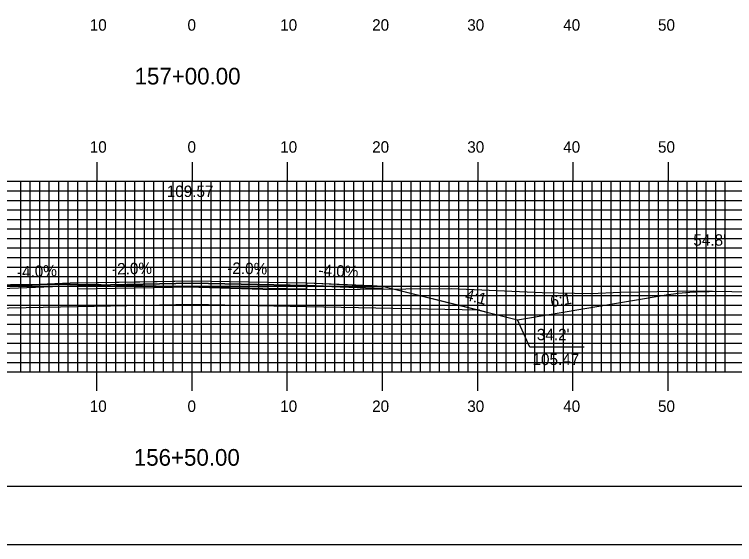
# Model space of a CAD drawing. Extents: x 1779499 to 1779842, y 442591 to 442811.
# Drawn here: x 1779646.2 to 1779721.8, y 442590.5 to 442646.2 of the extents above; entities that cross this region are included whole.
import ezdxf

# ---------------------------------------------------------------- set-up
doc = ezdxf.new("R2010")
doc.units = 0
for name, color, linetype in [('ANNOTATION', 7, 'Continuous'), ('BORDER', 7, 'Continuous'), ('D_Roadway_Centerline', 7, 'Continuous'), ('D_Roadway_Centerline_Text', 7, 'Continuous'), ('D_Roadway_Edge_Shoulder', 7, 'Continuous'), ('D_Roadway_Edge_TW', 7, 'Continuous'), ('D_Roadway_Pavement', 7, 'Continuous'), ('D_Roadway_SlopeLines', 7, 'Continuous'), ('D_Roadway_SubGrade', 7, 'Continuous'), ('D_Text_Standard', 7, 'Continuous'), ('H_V ANNOTATION', 7, 'Continuous'), ('MAJOR', 7, 'Continuous'), ('MINOR', 7, 'Continuous'), ('PLOT BOUNDARY', 7, 'Continuous'), ('S_Roadway_Centerline', 7, 'Continuous')]:
    doc.layers.add(name, color=color, linetype=linetype)

msp = doc.modelspace()

# ---------------------------------------------------------------- linework, layer by layer
at = {"layer": 'ANNOTATION'}
msp.add_lwpolyline([(1779706.005, 442611.258), (1779700.314, 442611.258), (1779699.016, 442614.134)], dxfattribs=at)
at = {"layer": 'BORDER'}
msp.add_lwpolyline([(1779515.242, 442596.665), (1779835.242, 442596.665), (1779835.242, 442806.665), (1779515.242, 442806.665)], close=True, dxfattribs=at)
at = {"layer": 'D_Roadway_Centerline'}
msp.add_lwpolyline([(1779644.842, 442617.677), (1779652.842, 442617.997), (1779659.369, 442618.128), (1779664.842, 442618.237), (1779676.841, 442617.997), (1779676.842, 442617.997), (1779683.762, 442617.72), (1779684.842, 442617.677), (1779695.016, 442615.134), (1779695.813, 442614.935), (1779699.016, 442614.134), (1779714.625, 442616.736), (1779714.626, 442616.736), (1779715.876, 442616.916), (1779717.126, 442617.04), (1779718.376, 442617.109), (1779719.139, 442617.117), (1779719.626, 442617.121)], dxfattribs=at)
at = {"layer": 'D_Roadway_Edge_Shoulder'}
for points in [[(1779652.842, 442617.997), (1779644.842, 442617.677), (1779644.842, 442617.427), (1779652.842, 442617.747)], [(1779676.842, 442617.997), (1779684.842, 442617.677), (1779684.842, 442617.427), (1779676.842, 442617.747)]]:
    msp.add_lwpolyline(points, close=True, dxfattribs=at)
at = {"layer": 'D_Roadway_Edge_TW'}
msp.add_lwpolyline([(1779652.842, 442617.747), (1779652.842, 442617.997), (1779664.842, 442618.237), (1779676.842, 442617.997), (1779676.842, 442617.747), (1779664.842, 442617.987)], close=True, dxfattribs=at)
at = {"layer": 'D_Roadway_Pavement'}
msp.add_lwpolyline([(1779652.842, 442617.331), (1779652.842, 442617.747), (1779664.842, 442617.987), (1779676.842, 442617.747), (1779676.842, 442617.331), (1779664.842, 442617.571)], close=True, dxfattribs=at)
at = {"layer": 'D_Roadway_SlopeLines'}
for points in [[(1779684.842, 442617.677), (1779699.016, 442614.134)], [(1779699.016, 442614.134), (1779714.626, 442616.736), (1779715.875, 442616.916), (1779717.126, 442617.04), (1779718.376, 442617.109), (1779719.625, 442617.121)]]:
    msp.add_lwpolyline(points, dxfattribs=at)
at = {"layer": 'D_Roadway_SubGrade'}
msp.add_lwpolyline([(1779652.842, 442615.497), (1779634.669, 442615.134), (1779644.842, 442617.677), (1779644.842, 442617.427), (1779652.842, 442617.747), (1779664.842, 442617.987), (1779676.842, 442617.747), (1779684.842, 442617.427), (1779684.842, 442617.677), (1779695.016, 442615.134), (1779676.842, 442615.497), (1779664.842, 442615.737)], close=True, dxfattribs=at)
at = {"layer": 'MAJOR'}
for p, q in [((1779654.842, 442630.669), (1779654.842, 442628.665)), ((1779664.842, 442630.669), (1779664.842, 442628.665)), ((1779674.842, 442630.669), (1779674.842, 442628.665)), ((1779684.842, 442630.669), (1779684.842, 442628.665)), ((1779694.842, 442630.669), (1779694.842, 442628.665)), ((1779704.842, 442630.669), (1779704.842, 442628.665)), ((1779714.842, 442630.669), (1779714.842, 442628.665)), ((1779524.842, 442628.665), (1779804.842, 442628.665)), ((1779524.842, 442628.665), (1779804.842, 442628.665)), ((1779654.842, 442608.665), (1779654.842, 442628.665)), ((1779664.842, 442608.665), (1779664.842, 442628.665)), ((1779674.842, 442608.665), (1779674.842, 442628.665)), ((1779684.842, 442608.665), (1779684.842, 442628.665)), ((1779694.842, 442608.665), (1779694.842, 442628.665)), ((1779704.842, 442608.665), (1779704.842, 442628.665)), ((1779714.842, 442608.665), (1779714.842, 442628.665)), ((1779524.842, 442623.665), (1779804.842, 442623.665)), ((1779524.842, 442618.665), (1779804.842, 442618.665)), ((1779524.842, 442613.665), (1779804.842, 442613.665)), ((1779524.842, 442608.665), (1779804.842, 442608.665)), ((1779524.842, 442608.665), (1779804.842, 442608.665)), ((1779654.842, 442606.661), (1779654.842, 442608.665)), ((1779664.842, 442606.661), (1779664.842, 442608.665)), ((1779674.842, 442606.661), (1779674.842, 442608.665)), ((1779684.842, 442606.661), (1779684.842, 442608.665)), ((1779694.842, 442606.661), (1779694.842, 442608.665)), ((1779704.842, 442606.661), (1779704.842, 442608.665)), ((1779714.842, 442606.661), (1779714.842, 442608.665))]:
    msp.add_line(p, q, dxfattribs=at)
at = {"layer": 'MINOR'}
for p, q in [((1779646.842, 442608.665), (1779646.842, 442628.665)), ((1779647.842, 442608.665), (1779647.842, 442628.665)), ((1779648.842, 442608.665), (1779648.842, 442628.665)), ((1779649.842, 442608.665), (1779649.842, 442628.665)), ((1779650.842, 442608.665), (1779650.842, 442628.665)), ((1779651.842, 442608.665), (1779651.842, 442628.665)), ((1779652.842, 442608.665), (1779652.842, 442628.665)), ((1779653.842, 442608.665), (1779653.842, 442628.665)), ((1779655.842, 442608.665), (1779655.842, 442628.665)), ((1779656.842, 442608.665), (1779656.842, 442628.665)), ((1779657.842, 442608.665), (1779657.842, 442628.665)), ((1779658.842, 442608.665), (1779658.842, 442628.665)), ((1779659.842, 442608.665), (1779659.842, 442628.665)), ((1779660.842, 442608.665), (1779660.842, 442628.665)), ((1779661.842, 442608.665), (1779661.842, 442628.665)), ((1779662.842, 442608.665), (1779662.842, 442628.665)), ((1779663.842, 442608.665), (1779663.842, 442628.665)), ((1779665.842, 442608.665), (1779665.842, 442628.665)), ((1779666.842, 442608.665), (1779666.842, 442628.665)), ((1779667.842, 442608.665), (1779667.842, 442628.665)), ((1779668.842, 442608.665), (1779668.842, 442628.665)), ((1779669.842, 442608.665), (1779669.842, 442628.665)), ((1779670.842, 442608.665), (1779670.842, 442628.665)), ((1779671.842, 442608.665), (1779671.842, 442628.665)), ((1779672.842, 442608.665), (1779672.842, 442628.665)), ((1779673.842, 442608.665), (1779673.842, 442628.665)), ((1779675.842, 442608.665), (1779675.842, 442628.665)), ((1779676.842, 442608.665), (1779676.842, 442628.665)), ((1779677.842, 442608.665), (1779677.842, 442628.665)), ((1779678.842, 442608.665), (1779678.842, 442628.665)), ((1779679.842, 442608.665), (1779679.842, 442628.665)), ((1779680.842, 442608.665), (1779680.842, 442628.665)), ((1779681.842, 442608.665), (1779681.842, 442628.665)), ((1779682.842, 442608.665), (1779682.842, 442628.665)), ((1779683.842, 442608.665), (1779683.842, 442628.665)), ((1779685.842, 442608.665), (1779685.842, 442628.665)), ((1779686.842, 442608.665), (1779686.842, 442628.665)), ((1779687.842, 442608.665), (1779687.842, 442628.665)), ((1779688.842, 442608.665), (1779688.842, 442628.665)), ((1779689.842, 442608.665), (1779689.842, 442628.665)), ((1779690.842, 442608.665), (1779690.842, 442628.665)), ((1779691.842, 442608.665), (1779691.842, 442628.665)), ((1779692.842, 442608.665), (1779692.842, 442628.665)), ((1779693.842, 442608.665), (1779693.842, 442628.665)), ((1779695.842, 442608.665), (1779695.842, 442628.665)), ((1779696.842, 442608.665), (1779696.842, 442628.665)), ((1779697.842, 442608.665), (1779697.842, 442628.665)), ((1779698.842, 442608.665), (1779698.842, 442628.665)), ((1779699.842, 442608.665), (1779699.842, 442628.665)), ((1779700.842, 442608.665), (1779700.842, 442628.665)), ((1779701.842, 442608.665), (1779701.842, 442628.665)), ((1779702.842, 442608.665), (1779702.842, 442628.665)), ((1779703.842, 442608.665), (1779703.842, 442628.665)), ((1779705.842, 442608.665), (1779705.842, 442628.665)), ((1779706.842, 442608.665), (1779706.842, 442628.665)), ((1779707.842, 442608.665), (1779707.842, 442628.665)), ((1779708.842, 442608.665), (1779708.842, 442628.665)), ((1779709.842, 442608.665), (1779709.842, 442628.665)), ((1779710.842, 442608.665), (1779710.842, 442628.665)), ((1779711.842, 442608.665), (1779711.842, 442628.665)), ((1779712.842, 442608.665), (1779712.842, 442628.665)), ((1779713.842, 442608.665), (1779713.842, 442628.665)), ((1779715.842, 442608.665), (1779715.842, 442628.665)), ((1779716.842, 442608.665), (1779716.842, 442628.665)), ((1779717.842, 442608.665), (1779717.842, 442628.665)), ((1779718.842, 442608.665), (1779718.842, 442628.665)), ((1779719.842, 442608.665), (1779719.842, 442628.665)), ((1779720.842, 442608.665), (1779720.842, 442628.665)), ((1779524.842, 442627.665), (1779804.842, 442627.665)), ((1779524.842, 442626.665), (1779804.842, 442626.665)), ((1779524.842, 442625.665), (1779804.842, 442625.665)), ((1779524.842, 442624.665), (1779804.842, 442624.665)), ((1779524.842, 442622.665), (1779804.842, 442622.665)), ((1779524.842, 442621.665), (1779804.842, 442621.665)), ((1779524.842, 442620.665), (1779804.842, 442620.665)), ((1779524.842, 442619.665), (1779804.842, 442619.665)), ((1779524.842, 442617.665), (1779804.842, 442617.665)), ((1779524.842, 442616.665), (1779804.842, 442616.665)), ((1779524.842, 442615.665), (1779804.842, 442615.665)), ((1779524.842, 442614.665), (1779804.842, 442614.665)), ((1779524.842, 442612.665), (1779804.842, 442612.665)), ((1779524.842, 442611.665), (1779804.842, 442611.665)), ((1779524.842, 442610.665), (1779804.842, 442610.665)), ((1779524.842, 442609.665), (1779804.842, 442609.665))]:
    msp.add_line(p, q, dxfattribs=at)
at = {"layer": 'PLOT BOUNDARY'}
msp.add_lwpolyline([(1779499.056, 442590.547), (1779839.056, 442590.547), (1779839.056, 442810.547), (1779499.056, 442810.547)], close=True, dxfattribs=at)
at = {"layer": 'S_Roadway_Centerline'}
msp.add_lwpolyline([(1779524.842, 442618.787), (1779530.014, 442618.672), (1779535.321, 442618.687), (1779548.073, 442619.115), (1779561.142, 442619.114), (1779569.915, 442618.82), (1779583.271, 442618.54), (1779593.483, 442618.248), (1779607.158, 442617.888), (1779610.65, 442617.932), (1779614.506, 442617.842), (1779630.747, 442617.757), (1779637.646, 442617.813), (1779653.858, 442617.87), (1779661.057, 442617.687), (1779672.256, 442617.348), (1779677.716, 442617.301), (1779692.079, 442617.401), (1779701.614, 442617.01), (1779706.692, 442616.876), (1779709.872, 442617.024), (1779717.478, 442617.159), (1779727.575, 442616.982)], dxfattribs=at)

# ---------------------------------------------------------------- texts
at = {"layer": 'ANNOTATION'}
for s, rotation, p in [('-4.0%', 2.29053, (1779646.474, 442618.544)), ('-2.0%', 1.14576, (1779656.448, 442618.87)), ('-2.0%', 358.8542, (1779668.528, 442618.964)), ('-4.0%', 357.70926, (1779678.094, 442618.749)), ('4:1', 345.9671, (1779693.439, 442616.227)), ('6:1', 9.46384, (1779702.572, 442615.454))]:
    msp.add_text(s, height=1.2, rotation=rotation, dxfattribs=at).set_placement(p)
for s, p in [("34.2'", (1779701.048, 442611.984)), ('105.47', (1779700.593, 442609.384))]:
    msp.add_text(s, height=1.2, dxfattribs=at).set_placement(p)
at = {"layer": 'D_Roadway_Centerline'}
for s, p in [('C', (1779664.837, 442618.237)), ('L', (1779664.842, 442618.23))]:
    msp.add_text(s, height=0.0146, dxfattribs=at).set_placement(p)
at = {"layer": 'D_Roadway_Centerline_Text'}
msp.add_text('109.57', height=1.2, dxfattribs=at).set_placement((1779662.178, 442627.014))
at = {"layer": 'D_Text_Standard'}
msp.add_text("54.8'", height=1.2, dxfattribs=at).set_placement((1779717.485, 442621.907))
at = {"layer": 'H_V ANNOTATION'}
for s, height, p in [('10', 1.2, (1779654.093, 442644.465)), ('0', 1.2, (1779664.36, 442644.465)), ('10', 1.2, (1779674.093, 442644.465)), ('20', 1.2, (1779683.75, 442644.465)), ('30', 1.2, (1779693.74, 442644.465)), ('40', 1.2, (1779703.815, 442644.465)), ('50', 1.2, (1779713.772, 442644.465)), ('157+00.00', 1.75, (1779658.803, 442638.821)), ('10', 1.2, (1779654.093, 442631.665)), ('0', 1.2, (1779664.36, 442631.665)), ('10', 1.2, (1779674.093, 442631.665)), ('20', 1.2, (1779683.75, 442631.665)), ('30', 1.2, (1779693.74, 442631.665)), ('40', 1.2, (1779703.815, 442631.665)), ('50', 1.2, (1779713.772, 442631.665)), ('10', 1.2, (1779654.093, 442604.465)), ('0', 1.2, (1779664.36, 442604.465)), ('10', 1.2, (1779674.093, 442604.465)), ('20', 1.2, (1779683.75, 442604.465)), ('30', 1.2, (1779693.74, 442604.465)), ('40', 1.2, (1779703.815, 442604.465)), ('50', 1.2, (1779713.772, 442604.465)), ('156+50.00', 1.75, (1779658.725, 442598.821))]:
    msp.add_text(s, height=height, dxfattribs=at).set_placement(p)

doc.saveas('drawing.dxf')
